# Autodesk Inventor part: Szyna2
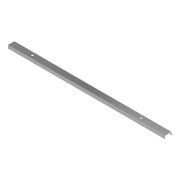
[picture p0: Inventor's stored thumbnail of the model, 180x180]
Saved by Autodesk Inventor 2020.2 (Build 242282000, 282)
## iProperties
Created: 2005-10
Part Number: Szyna2
Document SubType Name: Modeling
Designer: F.Stasiak
Density: 1 g/cm^3
Material: Ogólny
Appearance: Chrom — polerowany
Manager: www.cadconsulting.pl
Company: Fabian Stasiak CAD Consulting
Author: F.Stasiak
Subject: Zbiór ćwiczeń. Autodesk Inventor 2020. Kurs podstawowy
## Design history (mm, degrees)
sketch "Szkic1"
  geometry: L1 (-130.554, 3.058)-(129.446, 3.058); L2 (129.446, 3.058)-(129.446, -6.942); L3 (129.446, -6.942)-(-130.554, -6.942); L4 (-130.554, -6.942)-(-130.554, 3.058)
  constraints: 8 end point, 2 parallel, 1 horizontal, 1 perpendicular
  dimensions: "d0" = 260 distance of L2.end L3.end; "d1" = 10 distance of L3.end L1.start
extrude "Wyciągnięcie proste1" new body sketch "Szkic1" distance "d2" = 4; taper "d3" = 0 deg
fillet "Zaokrąglenie1" dims "d4" = 0.5
feature "Skorupa1" dims "d5" = 1
sketch "Szkic2"
  geometry: L1 (260, 9)-(260, 0) reference; L2 (0, 0)-(0, 9) reference; L3 (0, 4.5)-(260, 4.5); 2 further points
  constraints: 2 end point, 2 midpoint, 2 point on line
  dimensions: "d6" = 35 distance from line of L1 point (225, 4.5); "d7" = 180 distance of point (45, 4.5) point (225, 4.5)
hole "Otwór1" sketch "Szkic2" at (225, 4.5), (45, 4.5) diameter "d8" = 3.5; stored, may be unused: countersink angle "d12" = 120 deg, drill point angle "d14" = 118 deg; dims "d9" = 6, "d10" = 5, "d11" = 2, "d13" = 8
node "Bryła1"
node "Korpusy bryłowe"
node "Korpusy powierzchniowe"
